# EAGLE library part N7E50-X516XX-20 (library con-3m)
CONNECTOR PCMCIA-CompactFlash
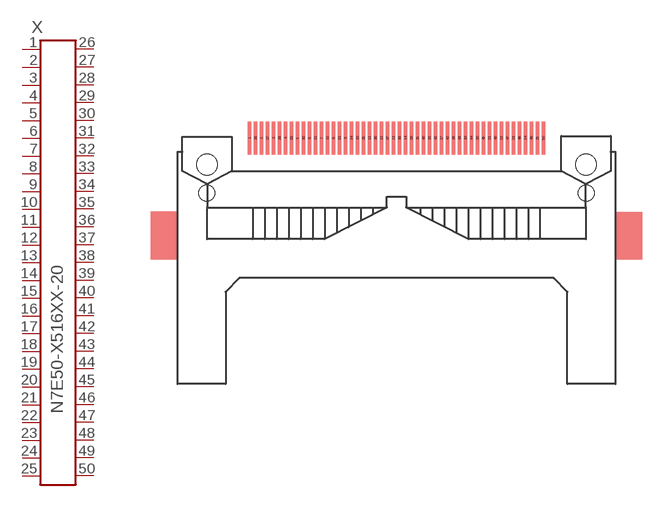
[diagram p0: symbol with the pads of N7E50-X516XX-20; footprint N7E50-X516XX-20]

Designator prefix X

## N7E50-X516XX-20 (OC_FARNELL: unknown; OC_NEWARK: unknown)  [N7E50-X516XX-20]
1  1  pas
2  2  pas
3  3  pas
4  4  pas
5  5  pas
6  6  pas
7  7  pas
8  8  pas
9  9  pas
10  10  pas
11  11  pas
12  12  pas
13  13  pas
14  14  pas
15  15  pas
16  16  pas
17  17  pas
18  18  pas
19  19  pas
20  20  pas
21  21  pas
22  22  pas
23  23  pas
24  24  pas
25  25  pas
26  26  pas
27  27  pas
28  28  pas
29  29  pas
30  30  pas
31  31  pas
32  32  pas
33  33  pas
34  34  pas
35  35  pas
36  36  pas
37  37  pas
38  38  pas
39  39  pas
40  40  pas
41  41  pas
42  42  pas
43  43  pas
44  44  pas
45  45  pas
46  46  pas
47  47  pas
48  48  pas
49  49  pas
50  50  pas

## Footprint N7E50-X516XX-20 (pad centres in mm)
CONNECTOR PCMCIA-CompactFlash Source: http://products3.3m.com
smd 0.4 x 3.5: 1 -15.557,2.81; 2 -14.287,2.81; 3 -13.018,2.81; 4 -11.748,2.81; 5 -10.477,2.81; 6 -9.207,2.81; 7 -7.938,2.81; 8 -6.668,2.81; 9 -5.397,2.81; 10 -4.128,2.81; 11 -2.857,2.81; 12 -1.587,2.81; 13 -0.318,2.81; 14 0.953,2.81; 15 2.223,2.81; 16 3.493,2.81; 17 4.763,2.81; 18 6.032,2.81; 19 7.303,2.81; 20 8.572,2.81; 21 9.842,2.81; 22 11.113,2.81; 23 12.383,2.81; 24 13.652,2.81; 25 14.922,2.81; 26 -14.922,2.81; 27 -13.652,2.81; 28 -12.383,2.81; 29 -11.113,2.81; 30 -9.842,2.81; 31 -8.572,2.81; 32 -7.303,2.81; 33 -6.032,2.81; 34 -4.763,2.81; 35 -3.493,2.81; 36 -2.223,2.81; 37 -0.953,2.81; 38 0.318,2.81; 39 1.587,2.81; 40 2.857,2.81; 41 4.128,2.81; 42 5.397,2.81; 43 6.668,2.81; 44 7.938,2.81; 45 9.207,2.81; 46 10.477,2.81; 47 11.748,2.81; 48 13.018,2.81; 49 14.287,2.81; 50 15.557,2.81
hole 1.7 at -20.08,-3
hole 1.7 at 20.08,-3
hole 2.2 at -20.08,0
hole 2.2 at 20.08,0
